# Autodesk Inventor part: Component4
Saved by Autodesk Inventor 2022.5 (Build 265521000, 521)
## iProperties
Created: 2024-12
Part Number: Component4
Material: Generic
Document SubType Name: Modeling
Designer: AdminForWorker
Density: 1 g/cm^3
Appearance: Default
Title: Component4
Author: AdminForWorker
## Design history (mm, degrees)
feature "Body1"
body "Solid1"
